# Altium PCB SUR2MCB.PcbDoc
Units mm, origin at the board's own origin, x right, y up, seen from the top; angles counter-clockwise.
Board outline 141 x 116 mm, 4 copper layers (Top Layer, GND, POWER, Bottom Layer), stack 1.491 mm thick; 0 components, 0 nets, 8 pads, 0 vias.
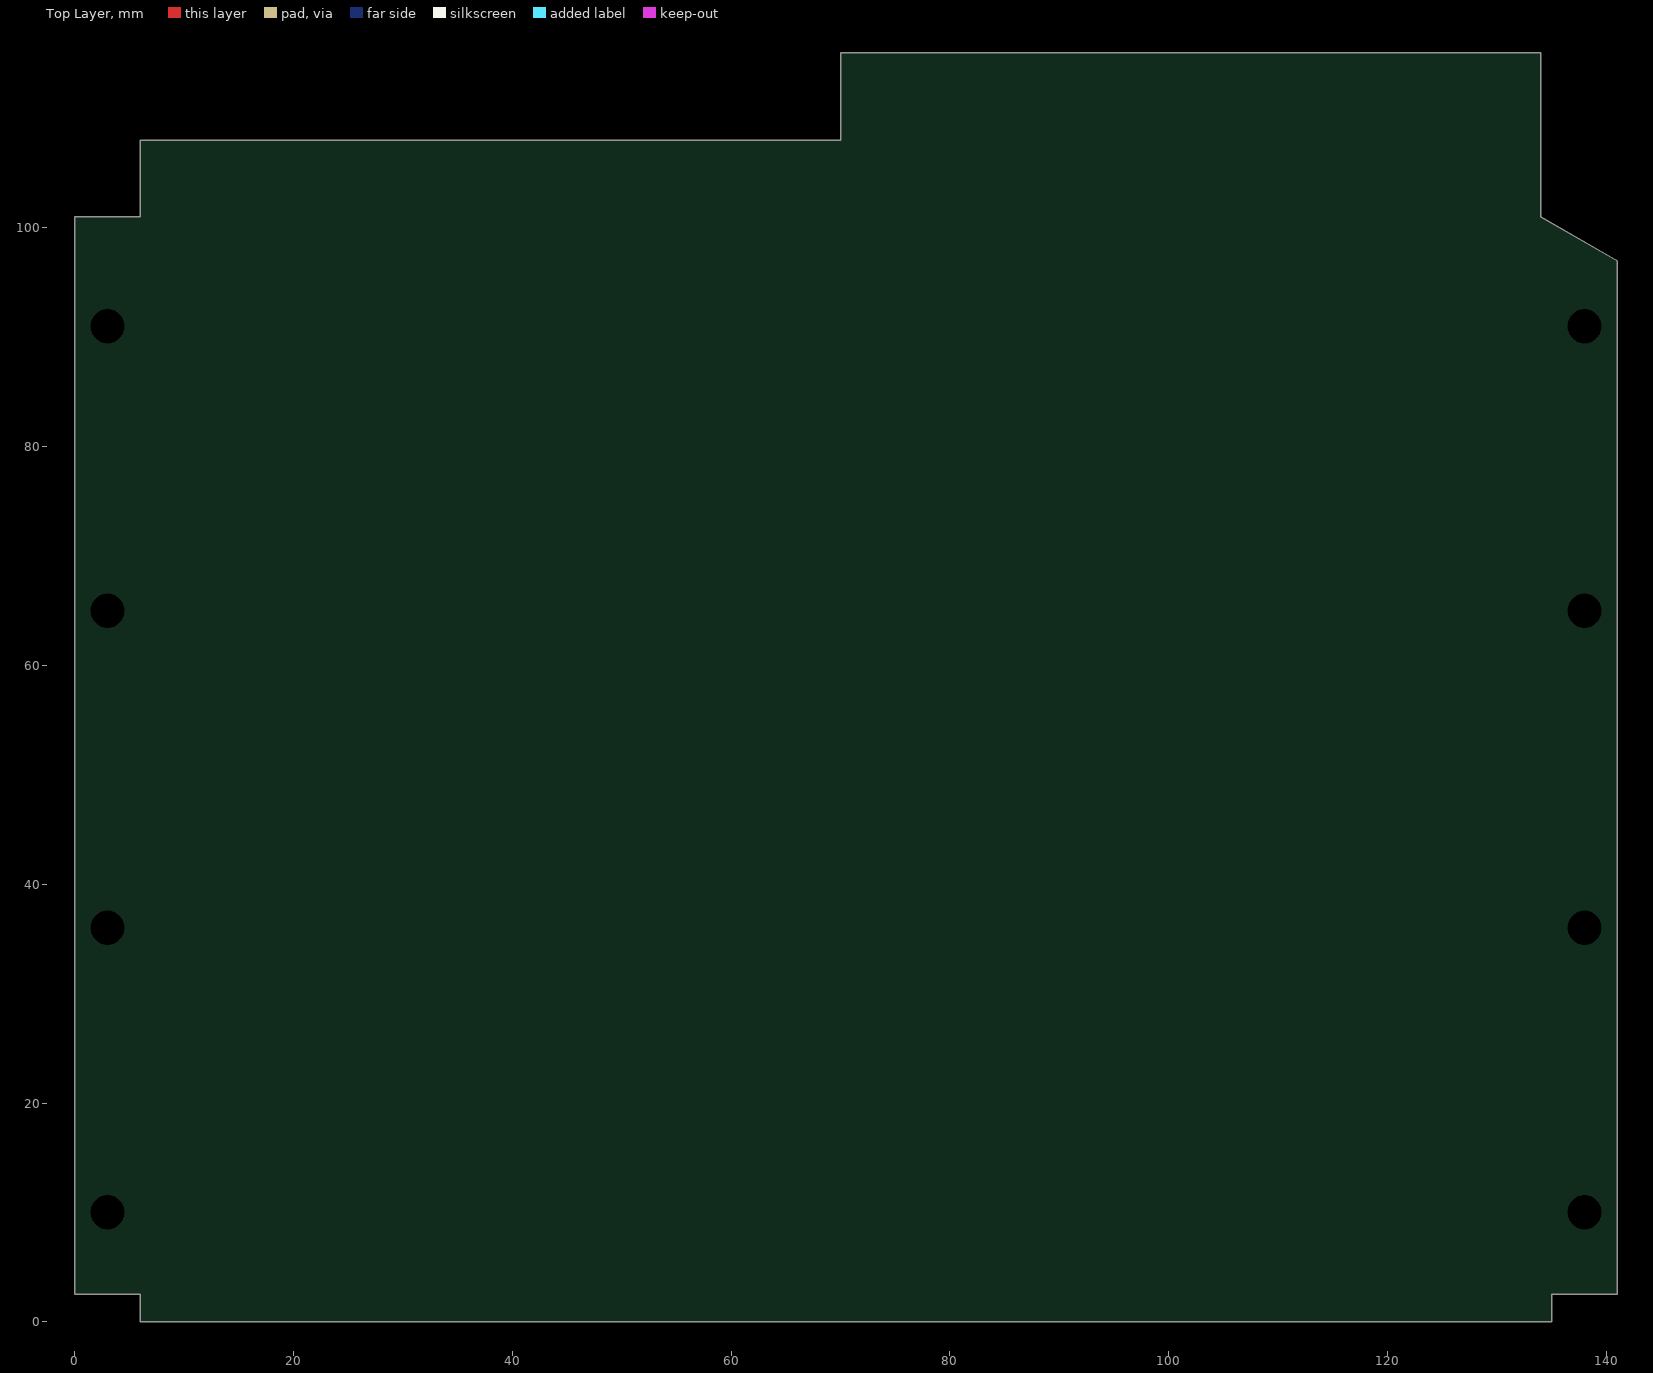
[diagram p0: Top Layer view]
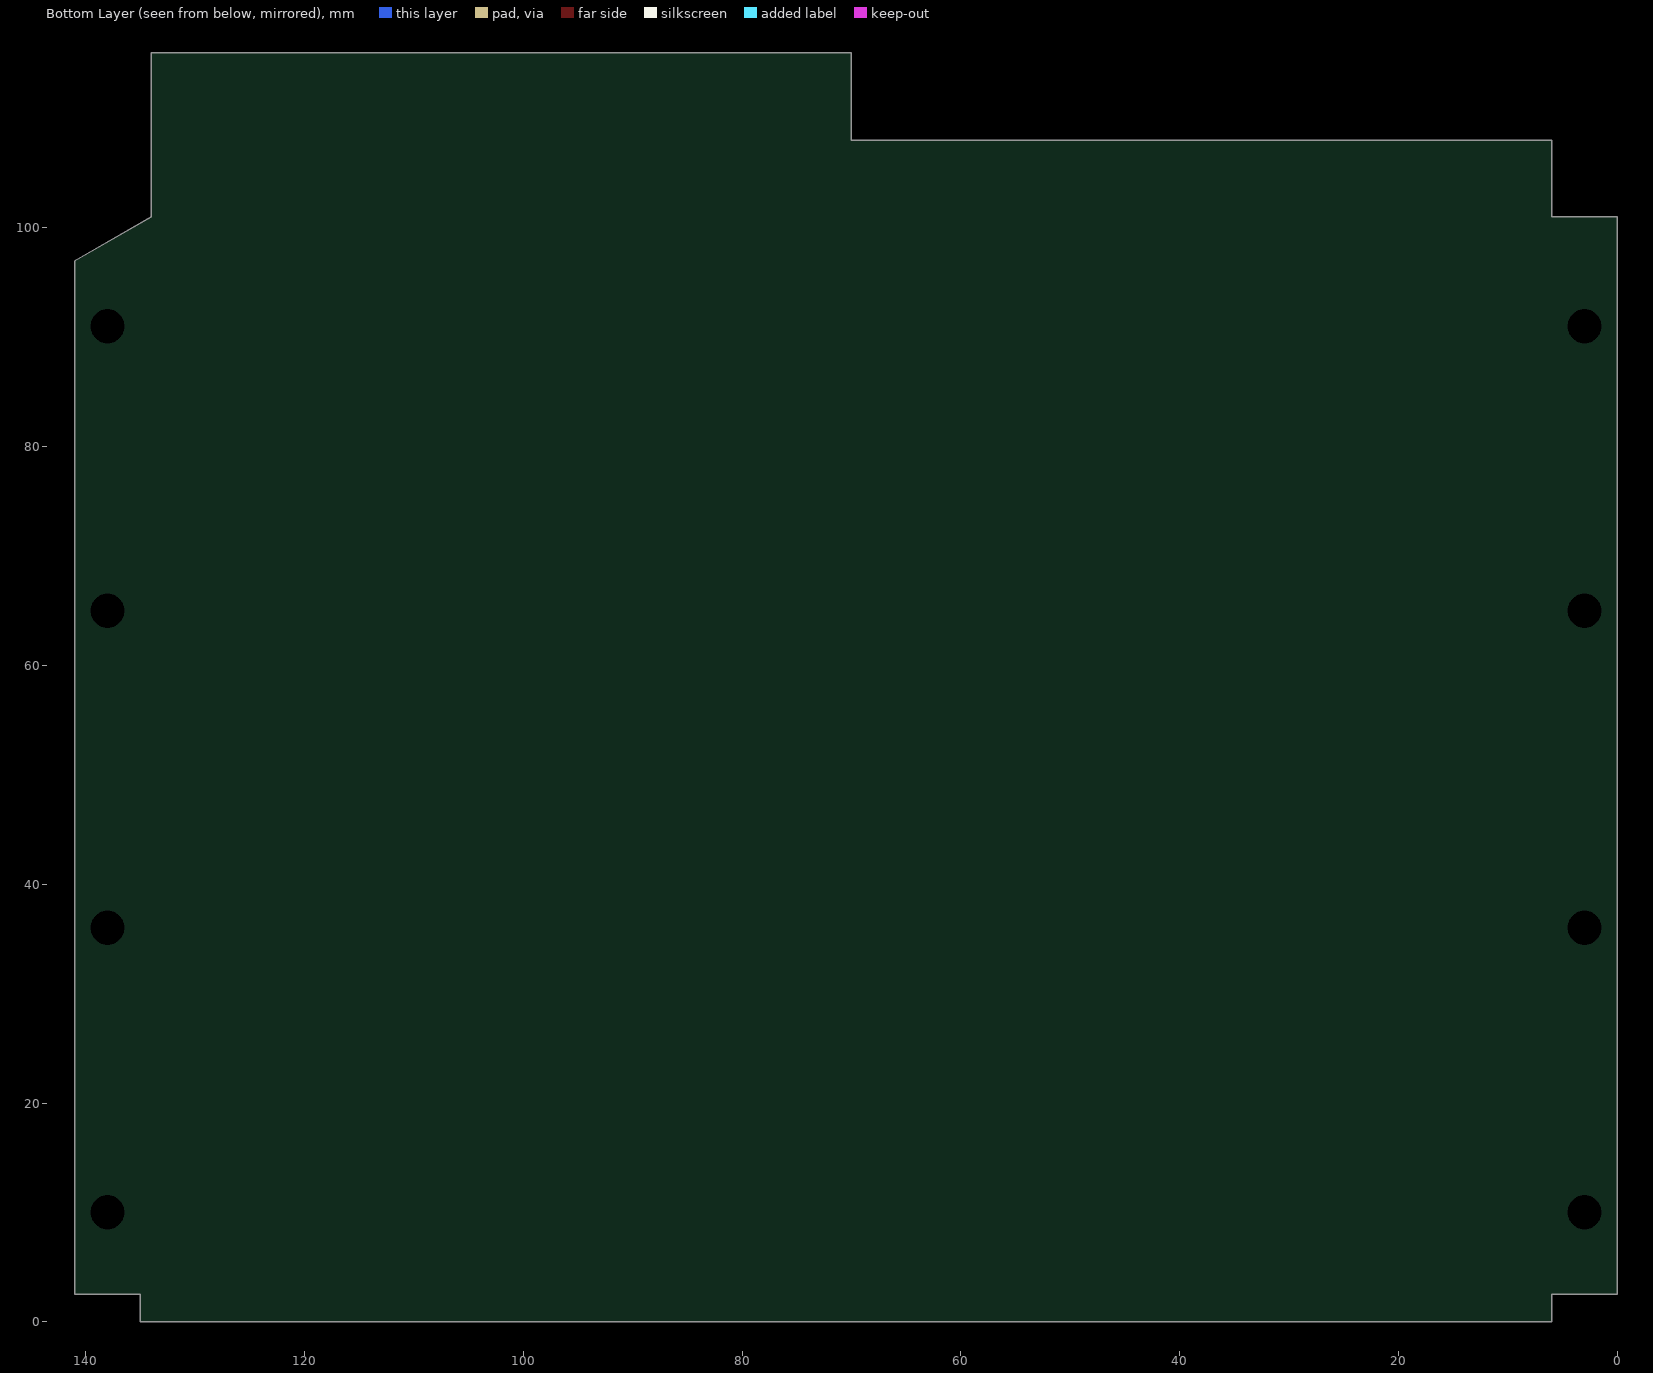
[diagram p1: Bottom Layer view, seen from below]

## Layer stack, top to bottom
Top Solder: solder mask 0.0102, Solder Resist, Dk 3.5
Top Layer: signal copper 0.035
Dielectric 3: prepreg 0.32, PP-006, Dk 4.1
GND: signal copper 0.035
CORE: core 0.71, Core-009, Dk 4.5
POWER: signal copper 0.035
Dielectric 1: dielectric 0.32, FR-4, Dk 4.8
Bottom Layer: signal copper 0.0356
Bottom Solder: solder mask 0.0102, Solder Resist, Dk 3.5

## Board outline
0.006,2.506 6.006,2.506 6.006,0.006 135.006,0.006 135.006,2.506 141.006,2.506 141.006,96.965 134.006,101.006 134.006,116.006 70.006,116.006 70.006,108.006 6.006,108.006 6.006,101.006 0.006,101.006

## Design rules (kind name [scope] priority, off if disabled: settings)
Clearance Clearance_RP [(InPadClass('RP_PADS'))] p1: gap=1.2 ignorepadtopadclearanceinfootprint=FALSE
Clearance "PWR LAYER" [OnLayer('POWER')] p2: gap=0.2 ignorepadtopadclearanceinfootprint=FALSE
Clearance "GND LAYER" [OnLayer('GROUND')] p3: gap=0.2 ignorepadtopadclearanceinfootprint=FALSE
Clearance "TOP LAYER" [OnLayer('TOP')] p4: gap=0.2 ignorepadtopadclearanceinfootprint=FALSE
Clearance "BOT LAYER" [OnLayer('BOTTOM')] p5: gap=0.2 ignorepadtopadclearanceinfootprint=FALSE
Clearance "TO MOUNT" [(InPadClass('MOUNT'))] p6: gap=0.8 ignorepadtopadclearanceinfootprint=FALSE except(0: Arc-Hole Track-Hole SMDPad-Hole THPad-Hole Via-Hole Fill-Hole Poly-Hole Region-Hole Text-Hole)
ComponentClearance [All] p1 off: gap=0.1 collisioncheckmode=3 verticalgap=0.254 showdistances=FALSE
DiffPairsRouting DiffPairsRouting_1 [All] p1: maxlimit=0.35 minlimit=0.2 mostfreqgap=0.25 toplayer_minwidth=0.2 toplayer_maxwidth=0.35 toplayer_prefwidth=0.25 midlayer1_minwidth=0.2 midlayer1_maxwidth=0.35 midlayer1_prefwidth=0.25 midlayer2_minwidth=0.2 midlayer2_maxwidth=0.35 midlayer2_prefwidth=0.25 bottomlayer_minwidth=0.2 bottomlayer_maxwidth=0.35 bottomlayer_prefwidth=0.25 maxuncoupledlength=12.7
FanoutControl Fanout_BGA [IsBGA] p1 off: bgadir=Out bgaviamode=Centered fanoutstyle=Auto fanoutdirection=Alternating viagrid=0.025 // Fanout_BGA (Default Rule)
FanoutControl Fanout_LCC [IsLCC] p2 off: bgadir=Out bgaviamode=Centered fanoutstyle=Auto fanoutdirection=Alternating viagrid=0.025 // Fanout_LCC (Default Rule)
FanoutControl Fanout_Default [All] p5 off: bgadir=Out bgaviamode=Centered fanoutstyle=Auto fanoutdirection=Alternating viagrid=0.025 // Fanout_Default (Default Rule)
HoleSize [All] p1: absolutevalues=TRUE maxlimit=3.5 minlimit=0.2 maxpercent=80.000 minpercent=20.000
HoleSize Testpoint [All] p2: absolutevalues=TRUE maxlimit=2.54 minlimit=0.025 maxpercent=80.000 minpercent=20.000
HoleSize TestPointUsage [All] p3 off: absolutevalues=TRUE maxlimit=2.54 minlimit=0.025 maxpercent=80.000 minpercent=20.000
HoleToHoleClearance [All] p1: gap=0 allowstackedmicrovias=TRUE
MinimumSolderMaskSliver [All] p1 off: minsoldermaskwidth=0.1
MinimumSolderMaskSliver SilkscreenOverComponentPads [All] p2 off: minsoldermaskwidth=0.254
PlaneConnect [All] p1: planeconnectstyle=Relief reliefexpansion=0.508 reliefentries=4 reliefconductorwidth=0.3 reliefairgap=0.3
PolygonConnect TERMO_POWER [All vs (InPadClass('POWER'))] p1: connectstyle=Direct reliefconductorwidth=0.254 reliefentries=4 polygonreliefangle="90 Angle" airgapwidth=0.254
PolygonConnect ALL_PADS [(InPadClass('All Pads'))] p2: connectstyle=Relief reliefconductorwidth=0.5 reliefentries=4 polygonreliefangle="90 Angle" airgapwidth=0.25
PolygonConnect [All] p3: connectstyle=Direct reliefconductorwidth=0.635 reliefentries=4 polygonreliefangle="90 Angle" airgapwidth=0.254
RoutingVias "POWER VIA" [(InNetClass('GROUND CLASS') AND InNetClass('POWER CLASS'))] p1: holewidth=0.7 width=1.4 viastyle="Through Hole" minholewidth=0.6 minwidth=1.1 maxholewidth=0.8 maxwidth=2
RoutingVias [All] p2: holewidth=0.4 width=0.8 viastyle="Through Hole" minholewidth=0.25 minwidth=0.5 maxholewidth=0.7 maxwidth=1.4
ShortCircuit [All] p1: allowed=TRUE
SilkToSilkClearance [All] p1: silktosilkclearance=0.2
SilkToSolderMaskClearance [IsPad] p1 off: minsilkscreentomaskgap=0.1 clearancetoexposedcopper=TRUE
SolderMaskExpansion [All] p1: expansion=0.01
Width [All] p1: maxlimit=5 minlimit=0.15 preferedwidth=0.5 midlayer1_minwidth=0.2 midlayer2_minwidth=0.2 minimp=50.000000 maximp=50.000000 favimp=50.000000
18 further rules are at their usual default settings.

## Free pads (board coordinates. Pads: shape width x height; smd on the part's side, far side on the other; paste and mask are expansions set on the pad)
  round 1 hole 3.15: -(3.006,10.006) -(3.006,36.006) -(3.006,65.006) -(3.006,91.006) -(138.006,10.006) -(138.006,36.006) -(138.006,65.006) -(138.006,91.006)

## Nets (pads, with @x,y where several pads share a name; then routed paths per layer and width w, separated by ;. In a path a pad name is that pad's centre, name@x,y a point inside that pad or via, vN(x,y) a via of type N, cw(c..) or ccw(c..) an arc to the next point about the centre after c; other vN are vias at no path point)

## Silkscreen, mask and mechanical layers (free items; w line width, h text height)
Mechanical 1:
  the board outline again, w0.013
